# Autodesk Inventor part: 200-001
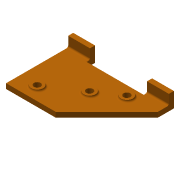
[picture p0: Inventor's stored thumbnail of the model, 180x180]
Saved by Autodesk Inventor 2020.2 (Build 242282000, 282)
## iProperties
Created: 2014-01
Part Number: 200-001
Material: Ogólny
Document SubType Name: Modeling
Designer: F.Stasiak
Density: 1 g/cm^3
Appearance: Pomarańczowa
Manager: www.cadconsulting.pl
Company: Fabian Stasiak CAD Consulting
Author: F.Stasiak
Subject: Zbiór ćwiczeń. Autodesk Inventor 2020. Kurs podstawowy
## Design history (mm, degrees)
sketch "Szkic1"
  geometry: L1 (-150, 15)-(150, 15); L2 (150, 15)-(150, 0); L3 (150, 0)-(-150, 0); L4 (-150, 0)-(-150, 15); 2 further points
  constraints: 8 end point, 2 parallel, 1 coincident, 1 horizontal, 1 midpoint, 1 perpendicular
  dimensions: "d0" = 300 distance of L2.end L3.end; "d1" = 15 distance of L1.end L2.end
extrude "Wyciągnięcie proste1" new body sketch "Szkic1" distance "d2" = 200; taper "d3" = 0 deg
sketch "Szkic2"
  geometry: L1 (0, 200)-(300, 200) reference; L2 (55.627, 162.916)-(215.9, 56.066); L3 (149.336, 100.442)-(215.9, 56.066); 2 further points
  constraints: 4 end point, 2 point on line, 1 collinear, 1 midpoint
  dimensions: "d4" = 192.625 distance of L2.start L2.end; "d28" = 80 distance of L3.start L2.end
hole "Otwór1" sketch "Szkic2" at (55.627, 162.916), (215.9, 56.066), (149.336, 100.442) diameter "d5" = 20; stored, may be unused: countersink angle "d9" = 90 deg, drill point angle "d11" = 118 deg; dims "d6" = 6, "d7" = 4, "d8" = 2, "d10" = 8
sketch "Szkic3"
  geometry: C1 r 10 at (55.627, -162.916) reference; C2 r 10 at (215.9, -56.066) reference; C3 r 17.5 at (215.9, -56.066); C4 r 17.5 at (149.336, -100.442); C5 r 17.5 at (55.627, -162.916); C6 r 10 at (149.336, -100.442) reference; 1 further point
  constraints: 3 centre point, 2 coincident, 1 concentric
  dimensions: "d12" = 35 diameter of C3; "d13" = 35 diameter of C4; "d14" = 35 diameter of C5
extrude "Wyciągnięcie proste2" join sketch "Szkic3" distance "d15" = 5; taper "d16" = 0 deg
sketch "Szkic5"
  geometry: L1 (0, 0)-(300, 0) reference; L2 (0, 0)-(0, -200) reference; L3 (300, 0)-(300, -200) reference; L4 (300, -15)-(0, -15); 1 further point
  constraints: 2 end point, 2 point on line, 1 perpendicular
  dimensions: "d21" = 15 distance between parallel lines of L4 L1
extrude "Wyciągnięcie proste4" join sketch "Szkic5" distance "d22" = 30; taper "d23" = 0 deg
sketch "Szkic4"
  geometry: L1 (300, 0)-(0, 0) reference; L2 (65, 25)-(235, 25); L3 (235, 25)-(235, 0); L4 (235, 0)-(65, 0); L5 (65, 0)-(65, 25); 2 further points
  constraints: 8 end point, 2 midpoint, 2 parallel, 1 horizontal, 1 perpendicular
  dimensions: "d17" = 170 distance of L2.start L2.end; "d18" = 25 distance of L2.end L3.end
extrude "Wyciągnięcie proste3" cut sketch "Szkic4" extent not by distance; stored distance "d19" = 5; taper "d20" = 0 deg
chamfer "Faza1" distance "d24" = 152; stored, may be unused: second distance "d25" = 2, angle "d26" = 45 deg
fillet "Zaokrąglenie1" dims "d27" = 5
node "Bryła1"
